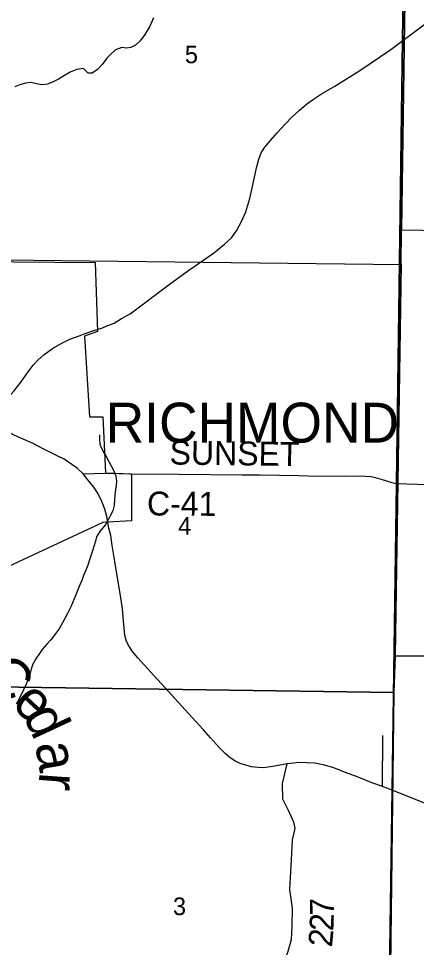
# Model space of a CAD drawing. Extents: x -19 to 40.8, y -1.8 to 26.1.
# Drawn here: x 3.517 to 4.462, y 18.273 to 20.478 of the extents above; entities that cross this region are included whole.
import ezdxf

# ---------------------------------------------------------------- set-up
doc = ezdxf.new("R2010")
doc.units = 0
for name, color, linetype in [('Default', 7, 'Continuous'), ('GM_X_City_Street', 7, 'Continuous'), ('GM_X_Corporation', 7, 'Continuous'), ('GM_X_County_Road_Text', 7, 'Continuous'), ('GM_X_Major_River_Text', 7, 'Continuous'), ('GM_X_Minor_River', 7, 'Continuous'), ('GM_X_Rail_Line', 7, 'Continuous'), ('GM_X_Section', 7, 'Continuous'), ('GM_X_Section_Text', 7, 'Continuous'), ('GM_X_State_Route', 7, 'Continuous'), ('GM_X_Township_Road_Text', 7, 'Continuous'), ('RW_P_Text', 7, 'Continuous')]:
    doc.layers.add(name, color=color, linetype=linetype)

msp = doc.modelspace()

# ---------------------------------------------------------------- linework, layer by layer
at = {"layer": 'Default'}
for points in [[(4.44, 20.9), (3.4313, 20.9), (3.4162, 19.9068), (4.4251, 19.8945), (4.4266, 19.9772)], [(5.4394, 20.9), (4.44, 20.9), (4.4266, 19.9772), (5.4217, 19.9611)]]:
    msp.add_lwpolyline(points, close=True, dxfattribs=at)
at = {"layer": 'GM_X_City_Street'}
msp.add_lwpolyline([(3.4088, 19.9016), (3.6992, 19.8991), (3.7041, 19.7358), (3.6736, 19.7245), (3.6855, 19.5329), (3.717, 19.5327), (3.7231, 19.3998), (3.7854, 19.398), (3.7853, 19.2857), (3.7292, 19.2827), (3.7171, 19.282), (3.4916, 19.1769)], dxfattribs=at)
at = {"layer": 'GM_X_Corporation'}
msp.add_line((3.7304, 19.399), (3.7805, 19.3976), dxfattribs=at)
for points in [[(3.6708, 19.3973), (3.7233, 19.3992), (3.7304, 19.399)], [(3.7805, 19.3976), (3.7856, 19.3975), (3.897, 19.3972), (4.0482, 19.395), (4.0911, 19.3949), (4.1824, 19.3936), (4.2273, 19.3924), (4.2913, 19.3926), (4.3403, 19.392), (4.3544, 19.3911), (4.3636, 19.3891), (4.38, 19.384), (4.3882, 19.3816), (4.3952, 19.3794), (4.3989, 19.3784)], [(4.3989, 19.3784), (4.4035, 19.3771), (4.4143, 19.3744), (4.4882, 19.3722)]]:
    msp.add_lwpolyline(points, dxfattribs=at)
at = {"layer": 'GM_X_Rail_Line'}
for points in [[(3.7251, 19.7478), (3.7442, 19.7554), (3.7617, 19.7662), (3.7821, 19.7776), (3.8749, 19.8467), (3.9215, 19.8814), (3.9797, 19.9216), (4.0064, 19.9432), (4.0224, 19.958), (4.0344, 19.9744), (4.0467, 19.9967), (4.0566, 20.0199), (4.0658, 20.0514), (4.0742, 20.087), (4.0821, 20.1242), (4.0875, 20.1448), (4.093, 20.1595), (4.1015, 20.1731), (4.1142, 20.1881), (4.1313, 20.2071), (4.1494, 20.2268), (4.1667, 20.2448), (4.1833, 20.26), (4.2004, 20.2749), (4.2173, 20.2871), (4.2366, 20.2998), (4.2682, 20.3179), (4.327, 20.3547), (4.4006, 20.4052), (4.4291, 20.4263), (4.4947, 20.4749)], [(3.6778, 19.7312), (3.6938, 19.7368), (3.7164, 19.7445), (3.7251, 19.7478)], [(3.4489, 19.5171), (3.4586, 19.5373), (3.4671, 19.5504), (3.4787, 19.5641), (3.5057, 19.5941), (3.5229, 19.6162), (3.5395, 19.6395), (3.5521, 19.6559), (3.5635, 19.6684), (3.5768, 19.68), (3.5974, 19.6951), (3.618, 19.707), (3.6387, 19.7171), (3.661, 19.7252), (3.6778, 19.7312)], [(3.5223, 19.4822), (3.5169, 19.4846), (3.4765, 19.5036), (3.4489, 19.5171)], [(3.7292, 19.2831), (3.7268, 19.2962), (3.7222, 19.3141), (3.7148, 19.332), (3.7052, 19.3514), (3.6961, 19.3663), (3.6818, 19.3836), (3.6708, 19.3973), (3.6567, 19.4107), (3.6433, 19.4202), (3.6254, 19.4324), (3.6072, 19.4408), (3.5774, 19.4564), (3.5515, 19.4693), (3.5223, 19.4822)], [(4.4834, 18.6148), (4.4574, 18.6255), (4.404, 18.6471), (4.381, 18.6552), (4.3586, 18.6633), (4.3235, 18.6775), (4.2933, 18.689), (4.2636, 18.7007), (4.2402, 18.7072), (4.2204, 18.7108), (4.2024, 18.7119), (4.1826, 18.7121), (4.1709, 18.7111), (4.1548, 18.7093), (4.1248, 18.7041), (4.0993, 18.7), (4.0862, 18.7002), (4.0704, 18.7021), (4.0563, 18.7059), (4.0433, 18.7103), (4.0317, 18.7158), (4.0188, 18.7246), (4.0079, 18.7341), (3.9942, 18.7476), (3.9729, 18.7711), (3.9561, 18.79), (3.9287, 18.8203), (3.8971, 18.8545), (3.8654, 18.8899), (3.8386, 18.9189), (3.8155, 18.9446), (3.8003, 18.9606), (3.7873, 18.9756), (3.7788, 18.989), (3.7734, 18.9998), (3.7696, 19.0143), (3.7673, 19.0402), (3.7639, 19.0768), (3.7586, 19.1133), (3.7513, 19.1556), (3.7456, 19.1893), (3.7393, 19.2276), (3.7359, 19.2514), (3.7317, 19.2686), (3.7294, 19.2821), (3.7292, 19.2831)]]:
    msp.add_lwpolyline(points, dxfattribs=at)
at = {"layer": 'GM_X_Section'}
for points in [[(3.8372, 20.4804), (3.8327, 20.4693), (3.8279, 20.4586), (3.8171, 20.4406), (3.8055, 20.4256), (3.7946, 20.4155), (3.784, 20.41), (3.773, 20.4084), (3.762, 20.4097), (3.7476, 20.4042), (3.7359, 20.3941), (3.7269, 20.3841), (3.7157, 20.3695), (3.7048, 20.3572), (3.6916, 20.349), (3.6821, 20.3488), (3.6713, 20.3597), (3.6557, 20.3576), (3.6398, 20.3509), (3.6258, 20.3435), (3.6118, 20.3349), (3.599, 20.3279), (3.5857, 20.3228), (3.5721, 20.3214), (3.5599, 20.3235), (3.5473, 20.3264), (3.5336, 20.3251), (3.5203, 20.3211), (3.5086, 20.3164)], [(3.7089, 19.4901), (3.709, 19.4806), (3.7103, 19.4681), (3.7142, 19.4582), (3.7205, 19.4469), (3.7259, 19.4371), (3.7318, 19.4257), (3.738, 19.4148), (3.7431, 19.4045), (3.7482, 19.3928), (3.7495, 19.3806), (3.7488, 19.3704), (3.7474, 19.3601), (3.7457, 19.3471), (3.7447, 19.3357), (3.7437, 19.3223), (3.7412, 19.3101), (3.7353, 19.2994), (3.7304, 19.2898), (3.7241, 19.2779), (3.7099, 19.2606), (3.7024, 19.2479), (3.6995, 19.238), (3.6955, 19.2254), (3.6926, 19.215), (3.6886, 19.2032), (3.6849, 19.1909), (3.6812, 19.181), (3.6768, 19.1691), (3.6713, 19.1565), (3.6669, 19.1447), (3.6628, 19.1339), (3.6576, 19.1224), (3.6529, 19.1106), (3.641, 19.0823), (3.634, 19.0677), (3.6273, 19.0543), (3.6214, 19.0443), (3.6132, 19.0301), (3.6042, 19.0171), (3.5934, 19.004), (3.5844, 18.9936), (3.5735, 18.9805), (3.5664, 18.9709), (3.5578, 18.9586), (3.5511, 18.9456), (3.5471, 18.9337), (3.5438, 18.9215), (3.5398, 18.9104), (3.535, 18.8982), (3.5291, 18.8848), (3.5191, 18.8652), (3.5113, 18.851)]]:
    msp.add_lwpolyline(points, dxfattribs=at)
at = {"layer": 'GM_X_State_Route'}
msp.add_line((4.381, 18.6552), (4.3819, 18.7769), dxfattribs=at)
for points in [[(4.3921, 17.8104), (4.3932, 17.8891), (4.4038, 18.6476), (4.4141, 19.3749), (4.4289, 20.4268), (4.4356, 20.9), (2.1, 20.9), (2.1, 15.8991), (2.1833, 15.8974), (3.0926, 15.8861), (3.7032, 15.8784), (3.9893, 15.872), (4.3628, 15.868), (4.3644, 15.9666), (4.3704, 16.384), (4.3769, 16.7589)], [(8.9, 15.8791), (8.9, 20.9), (4.4356, 20.9), (4.4289, 20.4268), (4.4141, 19.3749), (4.4038, 18.6476), (4.3932, 17.8891)], [(4.1459, 18.1916), (4.1415, 18.2116), (4.1429, 18.2249), (4.1569, 18.2649), (4.165, 18.2924), (4.1666, 18.3239), (4.1676, 18.3668), (4.161, 18.411), (4.163, 18.4395), (4.1655, 18.481), (4.1672, 18.5292), (4.1738, 18.5555), (4.1704, 18.571), (4.1581, 18.5988), (4.1443, 18.6251), (4.1435, 18.6626), (4.1548, 18.7093)]]:
    msp.add_lwpolyline(points, dxfattribs=at)
at = {"layer": 'RW_P_Text'}
for points in [[(4.4266, 19.9772), (5.4217, 19.9611), (5.3949, 18.9546), (4.411, 18.9653), (4.4251, 19.8945)], [(4.4251, 19.8945), (4.411, 18.9653), (4.4081, 18.8788), (3.4048, 18.893), (3.4162, 19.9068)], [(3.4048, 18.893), (4.4081, 18.8788), (4.397, 17.9674), (4.395, 17.8752), (3.3895, 17.8864)]]:
    msp.add_lwpolyline(points, close=True, dxfattribs=at)
msp.add_lwpolyline([(4.9335, 17.9644), (4.397, 17.9674), (4.4081, 18.8788), (4.411, 18.9653), (5.3949, 18.9546), (5.3629, 17.962), (5.0299, 17.9638)], dxfattribs=at)

# ---------------------------------------------------------------- texts
at = {"layer": 'GM_X_County_Road_Text'}
for s, rotation, p in [('SUNSET', 359.2744, (3.8755, 19.4199)), ('C-41', 359.6619, (3.8219, 19.2988))]:
    msp.add_text(s, height=0.05682, rotation=rotation, dxfattribs=at).set_placement(p)
at = {"layer": 'GM_X_Major_River_Text'}
msp.add_text('RICHMOND', height=0.0947, rotation=0, dxfattribs=at).set_placement((3.724, 19.4718))
at = {"layer": 'GM_X_Minor_River'}
for s, height, rotation, p in [('Ce', 0.09472, 316.9415, (3.4308, 18.9101)), ('d', 0.0947, 294.9474, (3.5268, 18.8249)), ('a', 0.0947, 279.954, (3.5561, 18.7556)), ('r', 0.0947, 265.9594, (3.567, 18.6909))]:
    msp.add_text(s, height=height, rotation=rotation, dxfattribs=at).set_placement(p)
at = {"layer": 'GM_X_Section_Text'}
for s, p in [('5', (3.9119, 20.3723)), ('4', (3.8961, 19.2533)), ('3', (3.8836, 18.3501))]:
    msp.add_text(s, height=0.0419, rotation=0, dxfattribs=at).set_placement(p)
at = {"layer": 'GM_X_Township_Road_Text'}
for s, rotation, p in [('7', 90.2412, (4.2657, 18.3488)), ('2', 88.1426, (4.2645, 18.3115)), ('2', 84.7276, (4.2611, 18.273))]:
    msp.add_text(s, height=0.0568, rotation=rotation, dxfattribs=at).set_placement(p)

doc.saveas('drawing.dxf')
